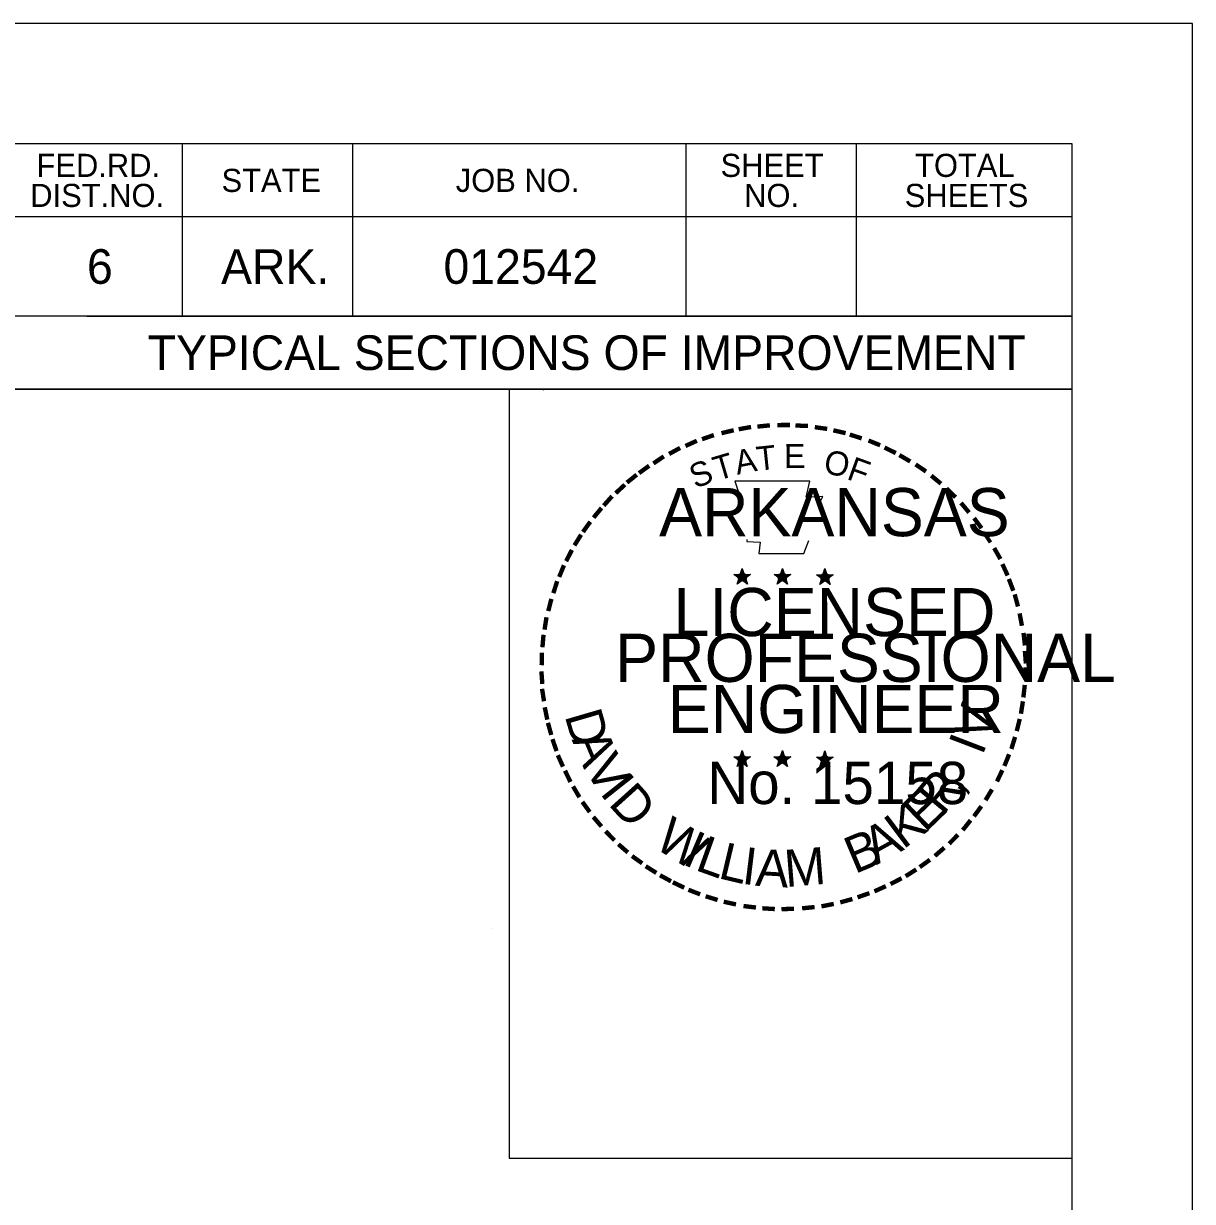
# Model space of a CAD drawing. Extents: x 34757 to 38214, y 51436 to 59430.
# Drawn here: x 36213.7 to 36456.6, y 52524.9 to 52769.6 of the extents above; entities that cross this region are included whole.
import ezdxf

# ---------------------------------------------------------------- set-up
doc = ezdxf.new("R2010")
doc.units = 0
for name, color, linetype in [('DSN_DRFT_Junk-No-Plot', 7, 'Continuous'), ('R_Border PE', 7, 'Continuous'), ('R_No Plot', 7, 'Continuous'), ('SHET_Annotations', 7, 'Continuous'), ('SHET_Border-Lines', 7, 'Continuous'), ('SHET_Border-Text', 7, 'Continuous'), ('SHET_Stamp-Prelim', 7, 'Continuous'), ('SHET_Stamp-Seal', 7, 'Continuous')]:
    doc.layers.add(name, color=color, linetype=linetype)

msp = doc.modelspace()

# ---------------------------------------------------------------- linework, layer by layer
at = {"layer": 'DSN_DRFT_Junk-No-Plot'}
msp.add_lwpolyline([(34756.64, 52769.61), (34756.64, 51669.61), (36456.64, 51669.61), (36456.64, 52769.61)], close=True, dxfattribs=at)
at = {"layer": 'R_Border PE'}
for p, q in [((36361.35, 52655.17), (36363.1, 52654.61)), ((36361.35, 52655.17), (36362.62, 52654.94)), ((36361.35, 52655.17), (36362.54, 52654.56)), ((36362.02, 52653.13), (36363.1, 52654.61)), ((36363.1, 52656.44), (36362.89, 52655.18)), ((36363.1, 52654.61), (36363.1, 52656.44)), ((36363.1, 52656.44), (36363.34, 52655.19)), ((36364.83, 52655.17), (36363.1, 52654.61)), ((36364.16, 52653.13), (36363.1, 52654.61)), ((36364.83, 52655.17), (36363.4, 52654.92)), ((36364.16, 52653.13), (36363.48, 52654.58)), ((36364.83, 52655.17), (36363.81, 52654.66)), ((36369.7, 52655.17), (36371.45, 52654.61)), ((36369.7, 52655.17), (36370.97, 52654.94)), ((36369.7, 52655.17), (36370.89, 52654.56)), ((36370.37, 52653.13), (36371.45, 52654.61)), ((36371.45, 52656.44), (36371.24, 52655.18)), ((36371.45, 52654.61), (36371.45, 52656.44)), ((36371.45, 52656.44), (36371.69, 52655.19)), ((36373.18, 52655.17), (36371.45, 52654.61)), ((36372.51, 52653.13), (36371.45, 52654.61)), ((36373.18, 52655.17), (36371.75, 52654.92)), ((36372.51, 52653.13), (36371.83, 52654.58)), ((36373.18, 52655.17), (36372.16, 52654.66)), ((36378.52, 52655.11), (36380.27, 52654.55)), ((36378.52, 52655.11), (36379.79, 52654.88)), ((36378.52, 52655.11), (36379.71, 52654.5)), ((36379.19, 52653.07), (36380.27, 52654.55)), ((36380.27, 52656.38), (36380.06, 52655.12)), ((36380.27, 52654.55), (36380.27, 52656.38)), ((36380.27, 52656.38), (36380.51, 52655.13)), ((36382, 52655.11), (36380.27, 52654.55)), ((36381.33, 52653.07), (36380.27, 52654.55)), ((36382, 52655.11), (36380.57, 52654.86)), ((36381.33, 52653.07), (36380.65, 52654.52)), ((36382, 52655.11), (36380.98, 52654.6)), ((36362.02, 52653.13), (36362.65, 52654.35)), ((36362.02, 52653.13), (36363.09, 52654.21)), ((36364.16, 52653.13), (36363.09, 52654.2)), ((36370.37, 52653.13), (36371, 52654.35)), ((36370.37, 52653.13), (36371.44, 52654.21)), ((36372.51, 52653.13), (36371.44, 52654.2)), ((36379.19, 52653.07), (36379.82, 52654.29)), ((36379.19, 52653.07), (36380.26, 52654.15)), ((36381.33, 52653.07), (36380.26, 52654.14)), ((36363.08, 52618.57), (36362.87, 52617.31)), ((36363.08, 52616.75), (36363.08, 52618.57)), ((36363.08, 52618.57), (36363.32, 52617.32)), ((36371.42, 52618.57), (36371.22, 52617.31)), ((36371.42, 52616.75), (36371.42, 52618.57)), ((36371.42, 52618.57), (36371.67, 52617.32)), ((36380.26, 52618.52), (36380.05, 52617.26)), ((36380.26, 52616.7), (36380.26, 52618.52)), ((36380.26, 52618.52), (36380.5, 52617.27)), ((36361.33, 52617.3), (36363.08, 52616.75)), ((36361.33, 52617.3), (36362.6, 52617.08)), ((36361.33, 52617.3), (36362.52, 52616.69)), ((36362, 52615.26), (36363.08, 52616.75)), ((36362, 52615.26), (36362.63, 52616.48)), ((36362, 52615.26), (36363.07, 52616.35)), ((36364.14, 52615.26), (36363.07, 52616.33)), ((36364.81, 52617.3), (36363.08, 52616.75)), ((36364.14, 52615.26), (36363.08, 52616.75)), ((36364.81, 52617.3), (36363.38, 52617.06)), ((36364.14, 52615.26), (36363.46, 52616.72)), ((36364.81, 52617.3), (36363.79, 52616.79)), ((36369.68, 52617.3), (36371.42, 52616.75)), ((36369.68, 52617.3), (36370.94, 52617.08)), ((36369.68, 52617.3), (36370.86, 52616.69)), ((36370.34, 52615.26), (36371.42, 52616.75)), ((36370.34, 52615.26), (36370.97, 52616.48)), ((36370.34, 52615.26), (36371.41, 52616.35)), ((36372.49, 52615.26), (36371.41, 52616.33)), ((36373.16, 52617.3), (36371.42, 52616.75)), ((36372.49, 52615.26), (36371.42, 52616.75)), ((36373.16, 52617.3), (36371.73, 52617.06)), ((36372.49, 52615.26), (36371.8, 52616.72)), ((36373.16, 52617.3), (36372.14, 52616.79)), ((36378.51, 52617.25), (36380.26, 52616.7)), ((36378.51, 52617.25), (36379.78, 52617.03)), ((36378.51, 52617.25), (36379.7, 52616.64)), ((36379.18, 52615.21), (36380.26, 52616.7)), ((36379.18, 52615.21), (36379.81, 52616.43)), ((36379.18, 52615.21), (36380.25, 52616.3)), ((36381.32, 52615.21), (36380.25, 52616.28)), ((36381.99, 52617.25), (36380.26, 52616.7)), ((36381.32, 52615.21), (36380.26, 52616.7)), ((36381.99, 52617.25), (36380.56, 52617.01)), ((36381.32, 52615.21), (36380.64, 52616.67)), ((36381.99, 52617.25), (36380.97, 52616.74))]:
    msp.add_line(p, q, dxfattribs=at)
for points in [[(36361.56, 52674.56), (36362.9, 52670.42)], [(36379.11, 52669.95), (36379.82, 52671.37), (36376.4, 52671.25), (36377.14, 52674.56), (36361.56, 52674.56)], [(36364.02, 52662.44), (36364.02, 52662.01), (36366.83, 52661.91), (36366.56, 52659.55), (36375.91, 52659.55), (36376.92, 52662.23)], [(36363.1, 52656.44), (36364.16, 52653.13), (36361.35, 52655.17), (36364.83, 52655.17), (36362.02, 52653.13), (36363.1, 52656.44)], [(36371.45, 52656.44), (36372.51, 52653.13), (36369.7, 52655.17), (36373.18, 52655.17), (36370.37, 52653.13), (36371.45, 52656.44)], [(36380.27, 52656.38), (36381.33, 52653.07), (36378.52, 52655.11), (36382, 52655.11), (36379.19, 52653.07), (36380.27, 52656.38)], [(36363.08, 52618.57), (36364.14, 52615.26), (36361.33, 52617.3), (36364.81, 52617.3), (36362, 52615.26), (36363.08, 52618.57)], [(36371.42, 52618.57), (36372.49, 52615.26), (36369.68, 52617.3), (36373.16, 52617.3), (36370.34, 52615.26), (36371.42, 52618.57)], [(36380.26, 52618.52), (36381.32, 52615.21), (36378.51, 52617.25), (36381.99, 52617.25), (36379.18, 52615.21), (36380.26, 52618.52)]]:
    msp.add_lwpolyline(points, dxfattribs=at)
for centre, radius in [((36363.09, 52654.61), 0.861), ((36363.09, 52654.61), 0.723), ((36363.09, 52654.61), 0.579), ((36363.09, 52654.61), 0.495), ((36363.09, 52654.61), 0.374), ((36363.09, 52654.61), 0.248), ((36363.09, 52654.61), 0.148), ((36371.44, 52654.61), 0.861), ((36371.44, 52654.61), 0.723), ((36371.44, 52654.61), 0.579), ((36371.44, 52654.61), 0.495), ((36371.44, 52654.61), 0.374), ((36371.44, 52654.61), 0.248), ((36371.44, 52654.61), 0.148), ((36380.26, 52654.55), 0.861), ((36380.26, 52654.55), 0.723), ((36380.26, 52654.55), 0.579), ((36380.26, 52654.55), 0.495), ((36380.26, 52654.55), 0.374), ((36380.26, 52654.55), 0.248), ((36380.26, 52654.55), 0.148), ((36363.07, 52616.74), 0.861), ((36363.07, 52616.74), 0.723), ((36363.07, 52616.74), 0.579), ((36363.07, 52616.74), 0.495), ((36363.07, 52616.74), 0.374), ((36363.07, 52616.74), 0.248), ((36363.07, 52616.74), 0.148), ((36371.42, 52616.74), 0.861), ((36371.42, 52616.74), 0.723), ((36371.42, 52616.74), 0.579), ((36371.42, 52616.74), 0.495), ((36371.42, 52616.74), 0.374), ((36371.42, 52616.74), 0.248), ((36371.42, 52616.74), 0.148), ((36380.25, 52616.69), 0.861), ((36380.25, 52616.69), 0.723), ((36380.25, 52616.69), 0.579), ((36380.25, 52616.69), 0.495), ((36380.25, 52616.69), 0.374), ((36380.25, 52616.69), 0.248), ((36380.25, 52616.69), 0.148)]:
    msp.add_circle(centre, radius, dxfattribs=at)
at = {"layer": 'R_No Plot'}
msp.add_line((36311.1, 52581.61), (36311.1, 52581.61), dxfattribs=at)
at = {"layer": 'SHET_Border-Lines'}
for p, q in [((36246.72, 52744.61), (36246.72, 52708.82)), ((36282.11, 52744.61), (36282.11, 52708.82)), ((36351.37, 52744.61), (36351.37, 52708.82)), ((36386.76, 52744.61), (36386.76, 52708.82)), ((36431.64, 52729.45), (36211.83, 52729.45)), ((36431.64, 52729.55), (36431.64, 52729.55)), ((36431.64, 52708.82), (36211.83, 52708.82)), ((36226.93, 52708.82), (36431.64, 52708.82)), ((36431.64, 52693.66), (36112.18, 52693.66))]:
    msp.add_line(p, q, dxfattribs=at)
for points in [[(34756.64, 51669.61), (36456.64, 51669.61), (36456.64, 52769.61), (34756.64, 52769.61)], [(34781.64, 51694.61), (36431.64, 51694.61), (36431.64, 52744.61), (34781.64, 52744.61)], [(36112.18, 52693.66), (36431.64, 52693.66), (36431.64, 52744.61), (36112.18, 52744.61)]]:
    msp.add_lwpolyline(points, close=True, dxfattribs=at)
at = {"layer": 'SHET_Stamp-Prelim'}
msp.add_lwpolyline([(36321.64, 52693.62), (36321.83, 52693.62), (36321.83, 52693.66), (36321.64, 52693.66)], close=True, dxfattribs=at)
at = {"layer": 'SHET_Stamp-Seal'}
msp.add_lwpolyline([(36314.63, 52533.94), (36431.64, 52533.94), (36431.64, 52693.66), (36314.63, 52693.66)], close=True, dxfattribs=at)

# ---------------------------------------------------------------- texts
at = {"layer": 'R_Border PE'}
for s, height, rotation, p in [('-', 8, 10.2193, (36362.43, 52682.21)), ('-', 8, 5.8968, (36366.08, 52682.76)), ('-', 8, 0.1862, (36369.94, 52683.12)), ('-', 8, 357.743, (36373.55, 52683.05)), ('-', 8, 352.1617, (36377.27, 52682.77)), ('-', 8, 19.1761, (36355.29, 52680.19)), ('-', 8, 13.6302, (36359.04, 52681.4)), ('-', 8, 347.2049, (36380.87, 52682.2)), ('-', 8, 342.3362, (36384.04, 52681.43)), ('-', 8, 28.7918, (36348.96, 52677.26)), ('-', 8, 24.3072, (36352.12, 52678.85)), ('T', 5, 6.0228, (36366.27, 52676.69)), ('E', 5, 0.8323, (36371.8, 52677.24)), ('-', 8, 337.8551, (36387.72, 52680.31)), ('-', 8, 334.1211, (36390.87, 52678.96)), ('-', 8, 34.0636, (36345.97, 52675.41)), ('T', 5, 16.4036, (36357.9, 52674.6)), ('A', 5, 11.2132, (36362.03, 52675.86)), ('O', 5, 350.4515, (36379.82, 52676.19)), ('F', 5, 340.0707, (36384.59, 52675.05)), ('-', 8, 329.6409, (36393.77, 52677.54)), ('-', 8, 36.2317, (36343.08, 52673.44)), ('S', 5, 21.594, (36353.33, 52672.95)), ('-', 8, 325.8627, (36396.98, 52675.74)), ('-', 8, 42.9622, (36338.54, 52669.46)), ('-', 8, 38.9507, (36340.7, 52671.55)), ('-', 8, 320.5297, (36400.03, 52673.61)), ('-', 8, 48.4231, (36336.3, 52667.07)), ('-', 8, 315.5786, (36403.03, 52671.17)), ('-', 8, 50.6142, (36334.28, 52664.64)), ('-', 8, 309.8797, (36405.87, 52668.42)), ('-', 8, 306.6522, (36408.5, 52665.41)), ('-', 8, 54.2325, (36332.22, 52661.81)), ('-', 8, 58.0706, (36330.59, 52659.17)), ('-', 7, 303.6753, (36410.93, 52662.57)), ('-', 8, 62.8713, (36329.03, 52656.1)), ('-', 8, 299.6684, (36412.52, 52659.53)), ('-', 8, 67.7743, (36327.73, 52653.05)), ('-', 8, 294.6628, (36414.14, 52656.47)), ('-', 8, 290.5728, (36415.43, 52653.59)), ('-', 8, 72.3945, (36326.64, 52649.9)), ('-', 8, 75.461, (36325.65, 52646.33)), ('-', 8, 285.1233, (36416.6, 52650.69)), ('-', 8, 280.5493, (36417.6, 52646.98)), ('-', 8, 81.2013, (36324.99, 52642.76)), ('-', 8, 85.1863, (36324.61, 52639.31)), ('-', 8, 276.5962, (36418.41, 52643.14)), ('-', 8, 89.0622, (36324.49, 52635.8)), ('-', 8, 274.3301, (36418.71, 52639.53)), ('-', 8, 94.1959, (36324.66, 52632.18)), ('-', 8, 269.9407, (36418.88, 52636.37)), ('-', 8, 98.9479, (36325.02, 52628.84)), ('-', 8, 263.5172, (36418.78, 52633.04)), ('-', 8, 101.7149, (36325.7, 52625.18)), ('V', 7.7, 72.6573, (36414.1, 52620.07)), ('-', 8, 260.9953, (36418.43, 52629.77)), ('D', 7.7, 286.2848, (36326.14, 52625.87)), ('-', 8, 255.7626, (36417.88, 52626.38)), ('-', 8, 105.4578, (36326.51, 52622.2)), ('-', 8, 109.0874, (36327.58, 52619.05)), ('A', 7.7, 292.7835, (36327.61, 52620.86)), ('I', 7.7, 69.0301, (36412.99, 52617.37)), ('-', 8, 252.8681, (36416.97, 52622.78)), ('-', 8, 114.0643, (36328.85, 52616.07)), ('V', 7.7, 300.7936, (36330.18, 52614.96)), ('-', 8, 247.8887, (36415.86, 52619.41)), ('-', 8, 115.7289, (36330.38, 52612.98)), ('I', 7.7, 308.3502, (36333.33, 52609.78)), ('R', 7.7, 50.3651, (36404.74, 52604.93)), ('-', 8, 244.6197, (36414.55, 52616.27)), ('-', 8, 120.4471, (36332.16, 52610.05)), ('D', 7.7, 311.9774, (36335.08, 52607.45)), ('E', 7.7, 44.0175, (36401.07, 52601.39)), (',', 7.7, 57.4684, (36408.36, 52609.34)), ('-', 8, 239.0712, (36412.58, 52612.51)), ('-', 8, 125.8934, (36334.18, 52607.24)), ('K', 7.7, 36.9143, (36396.53, 52597.94)), ('-', 8, 233.8452, (36410.57, 52609.24)), ('-', 8, 130.7181, (36336.49, 52604.48)), ('W', 7.7, 328.0731, (36344.48, 52598.62)), ('A', 7.7, 28.9042, (36390.94, 52594.75)), ('-', 8, 231.2538, (36408.42, 52606.41)), ('-', 8, 134.2238, (36339.07, 52601.76)), ('I', 7.7, 336.6877, (36350.41, 52595.07)), ('L', 7.7, 340.3149, (36353.06, 52593.85)), ('B', 7.7, 22.8589, (36386.46, 52592.88)), ('-', 8, 225.7653, (36406.02, 52603.59)), ('-', 8, 138.9338, (36341.7, 52599.44)), ('L', 7.7, 346.6625, (36357.86, 52592.13)), ('I', 7.7, 353.0101, (36362.82, 52590.95)), ('M', 7.7, 4.6473, (36372.13, 52590.23)), ('-', 8, 221.0851, (36403.41, 52601.05)), ('-', 8, 144.6463, (36344.48, 52597.41)), ('A', 7.7, 356.6373, (36365.7, 52590.52)), ('-', 8, 215.7363, (36400.67, 52598.69)), ('-', 8, 148.0898, (36347.28, 52595.55)), ('-', 8, 212.2491, (36398, 52596.75)), ('-', 8, 151.5704, (36350.18, 52593.93)), ('-', 8, 154.6002, (36352.79, 52592.69)), ('-', 8, 204.2516, (36392.09, 52593.43)), ('-', 8, 207.3568, (36395.21, 52595.02)), ('-', 8, 158.5612, (36355.91, 52591.42)), ('-', 8, 162.7983, (36359.34, 52590.36)), ('-', 8, 199.4643, (36388.93, 52592.04)), ('-', 8, 167.5555, (36362.92, 52589.54)), ('-', 8, 173.1155, (36366.78, 52588.99)), ('-', 8, 176.5183, (36370.52, 52588.72)), ('-', 8, 181.5918, (36374.24, 52588.82)), ('-', 8, 185.8167, (36378.28, 52589.2)), ('-', 8, 191.2858, (36381.96, 52589.86)), ('-', 8, 195.4743, (36385.61, 52590.85))]:
    msp.add_text(s, height=height, rotation=rotation, dxfattribs=at).set_placement(p)
for s, height, p in [('ARKANSAS', 10, (36345.82, 52663.12)), ('LICENSED', 10, (36348.81, 52642.37)), ('PROFESSIONAL', 10, (36336.69, 52632.85)), ('ENGINEER', 10, (36347.62, 52622.23)), ('No. 15158', 8.785, (36355.83, 52607.47)), ('AAMU', 0.0001, (36371.09, 52590.2))]:
    msp.add_text(s, height=height, dxfattribs=at).set_placement(p)
at = {"layer": 'SHET_Annotations'}
for s, p in [('6', (36226.93, 52715.54)), ('ARK.', (36254.8, 52715.54)), ('012542', (36301.01, 52715.54)), ('TYPICAL SECTIONS OF IMPROVEMENT', (36239.56, 52697.64))]:
    msp.add_text(s, height=7.2, dxfattribs=at).set_placement(p)
at = {"layer": 'SHET_Border-Text'}
for s, p in [('FED.RD.', (36216.44, 52737.75)), ('SHEET', (36358.59, 52737.75)), ('TOTAL', (36399, 52737.75)), ('STATE', (36254.89, 52734.63)), ('JOB NO.', (36303.56, 52734.63)), ('DIST.NO.', (36215.14, 52731.51)), ('NO.', (36363.48, 52731.51)), ('SHEETS', (36396.85, 52731.51))]:
    msp.add_text(s, height=4.8, dxfattribs=at).set_placement(p)
at = {"layer": 'SHET_Stamp-Prelim'}
for s, height, p in [('PRELIMINARY', 0.013, (36321.66, 52693.64)), ('SUBJECT TO REVISION', 0.009, (36321.67, 52693.63))]:
    msp.add_text(s, height=height, dxfattribs=at).set_placement(p)

doc.saveas('drawing.dxf')
